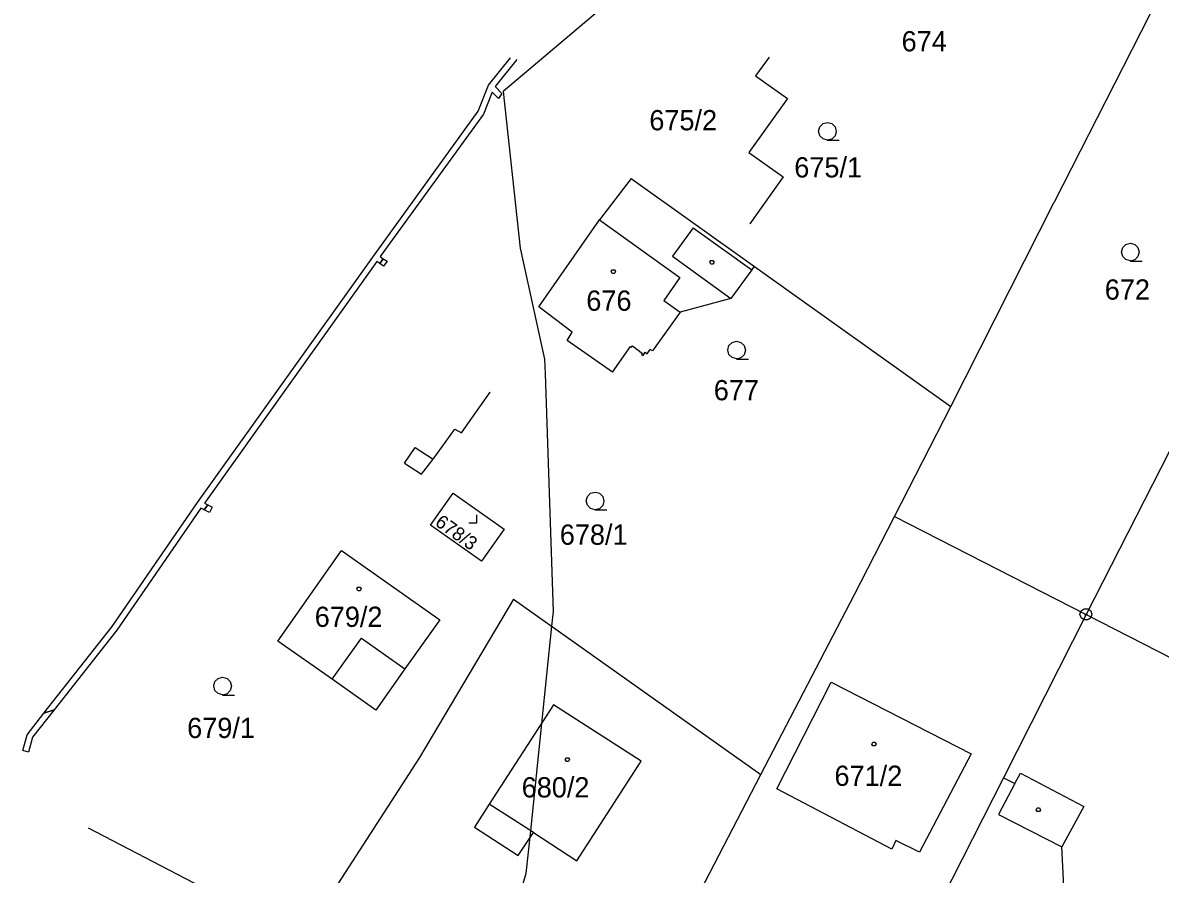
# Model space of a CAD drawing. Extents: x -759699 to -757730, y -1172308 to -1170857.
# Drawn here: x -758551.3 to -758455.8, y -1171287.4 to -1171215.9 of the extents above; entities that cross this region are included whole.
import ezdxf

# ---------------------------------------------------------------- set-up
doc = ezdxf.new("R2010")
doc.units = 0
for name, color, linetype in [('Vrstva 1', 7, 'Continuous'), ('Vrstva 11', 7, 'Continuous'), ('Vrstva 12', 7, 'Continuous'), ('Vrstva 13', 7, 'Continuous'), ('Vrstva 2', 7, 'Continuous'), ('Vrstva 3', 7, 'Continuous'), ('Vrstva 4', 7, 'Continuous'), ('Vrstva 5', 7, 'Continuous'), ('Vrstva 8', 7, 'Continuous')]:
    doc.layers.add(name, color=color, linetype=linetype)

msp = doc.modelspace()

# ---------------------------------------------------------------- linework, layer by layer
at = {"layer": 'Vrstva 1'}
for p, q in [((-758453.47, -1171208.89), (-758458.92, -1171219.58)), ((-758437.39, -1171217.28), (-758462.04, -1171265.57)), ((-758488.65, -1171218.77), (-758489.78, -1171220.35)), ((-758488.65, -1171218.77), (-758488.65, -1171218.77)), ((-758458.92, -1171219.58), (-758464.71, -1171230.94)), ((-758458.92, -1171219.58), (-758458.92, -1171219.58)), ((-758489.78, -1171220.35), (-758487.11, -1171222.26)), ((-758487.11, -1171222.26), (-758490.34, -1171226.79)), ((-758490.34, -1171226.79), (-758487.46, -1171228.84)), ((-758500.23, -1171228.97), (-758502.9, -1171232.43)), ((-758500.23, -1171228.97), (-758500.23, -1171228.97)), ((-758500.23, -1171228.97), (-758489.88, -1171236.35)), ((-758487.46, -1171228.84), (-758490.26, -1171232.78)), ((-758473.39, -1171248.12), (-758464.71, -1171230.94)), ((-758464.71, -1171230.94), (-758464.71, -1171230.94)), ((-758507.99, -1171239.75), (-758502.9, -1171232.43)), ((-758490.26, -1171232.78), (-758490.26, -1171232.78)), ((-758490.09, -1171236.64), (-758491.86, -1171239.04)), ((-758490.09, -1171236.64), (-758489.88, -1171236.35)), ((-758489.88, -1171236.35), (-758473.39, -1171248.12)), ((-758505.17, -1171241.87), (-758507.99, -1171239.75)), ((-758491.86, -1171239.04), (-758496.12, -1171240.18)), ((-758496.12, -1171240.18), (-758498.45, -1171243.44)), ((-758505.6, -1171242.57), (-758505.17, -1171241.87)), ((-758501.81, -1171245.24), (-758505.6, -1171242.57)), ((-758501.81, -1171245.24), (-758500.28, -1171243.08)), ((-758500.28, -1171243.08), (-758500.2, -1171243.14)), ((-758500.2, -1171243.14), (-758500.12, -1171243.02)), ((-758500.12, -1171243.02), (-758499.29, -1171243.65)), ((-758499.29, -1171243.65), (-758499.35, -1171243.73)), ((-758499.35, -1171243.73), (-758499.23, -1171243.82)), ((-758499.23, -1171243.82), (-758499.05, -1171243.56)), ((-758499.05, -1171243.56), (-758498.89, -1171243.68)), ((-758498.89, -1171243.68), (-758498.62, -1171243.32)), ((-758498.45, -1171243.44), (-758498.62, -1171243.32)), ((-758514.46, -1171250.32), (-758512.08, -1171246.92)), ((-758512.08, -1171246.92), (-758512.08, -1171246.92)), ((-758478.12, -1171257.35), (-758473.39, -1171248.12)), ((-758516.86, -1171252.53), (-758515.03, -1171250.02)), ((-758515.03, -1171250.02), (-758514.46, -1171250.32)), ((-758519.27, -1171252.86), (-758519.27, -1171252.86)), ((-758519.27, -1171252.86), (-758517.83, -1171253.8)), ((-758517.83, -1171253.8), (-758516.86, -1171252.53)), ((-758517.09, -1171258.09), (-758515.18, -1171255.4)), ((-758515.18, -1171255.4), (-758510.9, -1171258.42)), ((-758512.8, -1171261.11), (-758517.09, -1171258.09)), ((-758481.47, -1171263.91), (-758478.12, -1171257.35)), ((-758478.12, -1171257.35), (-758462.04, -1171265.57)), ((-758510.9, -1171258.42), (-758512.8, -1171261.11)), ((-758529.9, -1171267.82), (-758524.55, -1171260.21)), ((-758524.55, -1171260.21), (-758516.29, -1171266.02)), ((-758510.1, -1171264.29), (-758518.01, -1171277.59)), ((-758510.1, -1171264.29), (-758510.1, -1171264.29)), ((-758510.1, -1171264.29), (-758489.33, -1171279.02)), ((-758489.33, -1171279.02), (-758481.47, -1171263.91)), ((-758481.47, -1171263.91), (-758481.47, -1171263.91)), ((-758462.04, -1171265.57), (-758468.98, -1171279.28)), ((-758462.04, -1171265.57), (-758446, -1171273.82)), ((-758516.29, -1171266.02), (-758519.22, -1171270.15)), ((-758525.34, -1171271.02), (-758529.9, -1171267.82)), ((-758519.22, -1171270.15), (-758521.66, -1171273.6)), ((-758521.66, -1171273.6), (-758525.34, -1171271.02)), ((-758488.01, -1171280.22), (-758483.44, -1171271.25)), ((-758483.44, -1171271.25), (-758471.67, -1171277.27)), ((-758506.74, -1171273.15), (-758512.14, -1171281.5)), ((-758499.39, -1171277.9), (-758506.74, -1171273.15)), ((-758518.01, -1171277.59), (-758527.85, -1171292.83)), ((-758504.79, -1171286.25), (-758499.39, -1171277.9)), ((-758471.67, -1171277.27), (-758476.01, -1171285.54)), ((-758497.35, -1171294.4), (-758489.33, -1171279.02)), ((-758468.01, -1171279.77), (-758467.55, -1171278.89)), ((-758467.55, -1171278.89), (-758462.22, -1171281.69)), ((-758468.98, -1171279.28), (-758477.15, -1171295.43)), ((-758468.98, -1171279.28), (-758468.01, -1171279.77)), ((-758478.35, -1171285.27), (-758488.01, -1171280.22)), ((-758508.44, -1171283.89), (-758512.14, -1171281.5)), ((-758462.22, -1171281.69), (-758464.06, -1171285.09)), ((-758545.78, -1171283.53), (-758545.78, -1171283.53)), ((-758545.78, -1171283.53), (-758545.78, -1171283.53)), ((-758527.85, -1171292.83), (-758545.78, -1171283.53)), ((-758508.44, -1171283.89), (-758504.79, -1171286.25)), ((-758478, -1171284.55), (-758478.35, -1171285.27)), ((-758476.01, -1171285.54), (-758478, -1171284.55)), ((-758463.83, -1171289.75), (-758464.06, -1171285.09))]:
    msp.add_line(p, q, dxfattribs=at)
at = {"layer": 'Vrstva 11'}
for p, q in [((-758128.76, -1170897.97), (-758510.97, -1171221.67)), ((-758510.97, -1171221.67), (-758509.56, -1171234.81)), ((-758509.56, -1171234.81), (-758507.5, -1171244.14)), ((-758507.5, -1171244.14), (-758507.46, -1171245.38)), ((-758507.46, -1171245.38), (-758506.79, -1171265.32)), ((-758506.79, -1171265.32), (-758506.92, -1171266.55)), ((-758506.92, -1171266.55), (-758507.76, -1171274.73)), ((-758507.76, -1171274.73), (-758508.69, -1171283.73)), ((-758508.69, -1171283.73), (-758509.06, -1171287.33)), ((-758509.06, -1171287.33), (-758512.09, -1171297.46))]:
    msp.add_line(p, q, dxfattribs=at)
at = {"layer": 'Vrstva 12'}
for p, q in [((-758488.65, -1171218.77), (-758489.78, -1171220.35)), ((-758488.65, -1171218.77), (-758488.65, -1171218.77)), ((-758489.78, -1171220.35), (-758487.11, -1171222.26)), ((-758487.11, -1171222.26), (-758490.34, -1171226.79)), ((-758490.34, -1171226.79), (-758487.46, -1171228.84)), ((-758487.46, -1171228.84), (-758490.26, -1171232.78)), ((-758507.99, -1171239.75), (-758502.9, -1171232.43)), ((-758502.9, -1171232.43), (-758496.13, -1171237.29)), ((-758490.26, -1171232.78), (-758490.26, -1171232.78)), ((-758496.13, -1171237.29), (-758497.5, -1171239.2)), ((-758505.17, -1171241.87), (-758507.99, -1171239.75)), ((-758497.5, -1171239.2), (-758496.12, -1171240.18)), ((-758496.12, -1171240.18), (-758498.45, -1171243.44)), ((-758505.6, -1171242.57), (-758505.17, -1171241.87)), ((-758501.81, -1171245.24), (-758505.6, -1171242.57)), ((-758501.81, -1171245.24), (-758500.28, -1171243.08)), ((-758500.28, -1171243.08), (-758500.2, -1171243.14)), ((-758500.2, -1171243.14), (-758500.12, -1171243.02)), ((-758500.12, -1171243.02), (-758499.29, -1171243.65)), ((-758499.29, -1171243.65), (-758499.35, -1171243.73)), ((-758499.35, -1171243.73), (-758499.23, -1171243.82)), ((-758499.23, -1171243.82), (-758499.05, -1171243.56)), ((-758499.05, -1171243.56), (-758498.89, -1171243.68)), ((-758498.89, -1171243.68), (-758498.62, -1171243.32)), ((-758498.45, -1171243.44), (-758498.62, -1171243.32)), ((-758514.46, -1171250.32), (-758512.08, -1171246.92)), ((-758512.08, -1171246.92), (-758512.08, -1171246.92)), ((-758516.86, -1171252.53), (-758515.03, -1171250.02)), ((-758515.03, -1171250.02), (-758514.46, -1171250.32)), ((-758519.27, -1171252.86), (-758518.35, -1171251.55)), ((-758518.35, -1171251.55), (-758516.86, -1171252.53)), ((-758519.27, -1171252.86), (-758519.27, -1171252.86)), ((-758529.9, -1171267.82), (-758524.55, -1171260.21)), ((-758524.55, -1171260.21), (-758516.29, -1171266.02)), ((-758516.29, -1171266.02), (-758519.22, -1171270.15)), ((-758525.34, -1171271.02), (-758522.87, -1171267.57)), ((-758522.87, -1171267.57), (-758519.22, -1171270.15)), ((-758525.34, -1171271.02), (-758529.9, -1171267.82)), ((-758488.01, -1171280.22), (-758483.44, -1171271.25)), ((-758483.44, -1171271.25), (-758471.67, -1171277.27)), ((-758506.74, -1171273.15), (-758512.14, -1171281.5)), ((-758499.39, -1171277.9), (-758506.74, -1171273.15)), ((-758504.79, -1171286.25), (-758499.39, -1171277.9)), ((-758471.67, -1171277.27), (-758476.01, -1171285.54)), ((-758478.35, -1171285.27), (-758488.01, -1171280.22)), ((-758508.44, -1171283.89), (-758512.14, -1171281.5)), ((-758508.44, -1171283.89), (-758504.79, -1171286.25)), ((-758478, -1171284.55), (-758478.35, -1171285.27)), ((-758476.01, -1171285.54), (-758478, -1171284.55))]:
    msp.add_line(p, q, dxfattribs=at)
at = {"layer": 'Vrstva 13'}
for p, q in [((-758512.22, -1171221.14), (-758510.35, -1171218.82)), ((-758510.35, -1171218.82), (-758510.35, -1171218.82)), ((-758509.83, -1171218.98), (-758511.66, -1171221.25)), ((-758509.83, -1171218.98), (-758509.83, -1171218.98)), ((-758513.08, -1171223.32), (-758512.22, -1171221.14)), ((-758511.91, -1171221.72), (-758512.64, -1171223.56)), ((-758511.38, -1171222.25), (-758511.91, -1171221.72)), ((-758511.66, -1171221.25), (-758511.08, -1171221.84)), ((-758511.08, -1171221.84), (-758511.38, -1171222.25)), ((-758521.93, -1171235.56), (-758513.08, -1171223.32)), ((-758512.64, -1171223.56), (-758521.29, -1171235.52)), ((-758536.63, -1171256.17), (-758521.93, -1171235.56)), ((-758521.58, -1171235.93), (-758536.06, -1171256.22)), ((-758521.33, -1171236.11), (-758521.58, -1171235.93)), ((-758521.33, -1171236.11), (-758521.04, -1171235.7)), ((-758521.04, -1171235.7), (-758521.33, -1171236.11)), ((-758521.02, -1171236.33), (-758521.33, -1171236.11)), ((-758521.29, -1171235.52), (-758521.04, -1171235.7)), ((-758521.04, -1171235.7), (-758520.72, -1171235.92)), ((-758520.72, -1171235.92), (-758521.02, -1171236.33)), ((-758543.81, -1171266.58), (-758536.63, -1171256.17)), ((-758536.35, -1171256.64), (-758543.41, -1171266.88)), ((-758536.07, -1171256.79), (-758536.35, -1171256.64)), ((-758536.07, -1171256.79), (-758535.77, -1171256.38)), ((-758535.77, -1171256.38), (-758536.07, -1171256.79)), ((-758535.64, -1171257.02), (-758536.07, -1171256.79)), ((-758536.06, -1171256.22), (-758535.77, -1171256.38)), ((-758535.77, -1171256.38), (-758535.4, -1171256.57)), ((-758535.4, -1171256.57), (-758535.64, -1171257.02)), ((-758549.53, -1171273.86), (-758543.81, -1171266.58)), ((-758543.41, -1171266.88), (-758548.67, -1171273.57)), ((-758550.95, -1171275.67), (-758549.53, -1171273.86)), ((-758548.67, -1171273.57), (-758550.49, -1171275.89)), ((-758548.67, -1171273.57), (-758549.53, -1171273.86)), ((-758549.53, -1171273.86), (-758548.67, -1171273.57)), ((-758551.31, -1171277.01), (-758550.95, -1171275.67)), ((-758550.49, -1171275.89), (-758550.83, -1171277.14)), ((-758550.83, -1171277.14), (-758551.31, -1171277.01))]:
    msp.add_line(p, q, dxfattribs=at)
at = {"layer": 'Vrstva 3'}
for points in [[(-758483.74, -1171225.74), (-758484.12, -1171225.64), (-758484.39, -1171225.37), (-758484.49, -1171225), (-758484.39, -1171224.63), (-758484.12, -1171224.36), (-758483.75, -1171224.26), (-758483.38, -1171224.36), (-758483.11, -1171224.63), (-758483.01, -1171225.01), (-758483.11, -1171225.39), (-758483.38, -1171225.66), (-758483.76, -1171225.76), (-758482.76, -1171225.76)], [(-758458.31, -1171235.88), (-758458.69, -1171235.78), (-758458.96, -1171235.51), (-758459.06, -1171235.14), (-758458.96, -1171234.77), (-758458.69, -1171234.5), (-758458.32, -1171234.4), (-758457.95, -1171234.5), (-758457.68, -1171234.77), (-758457.58, -1171235.15), (-758457.68, -1171235.53), (-758457.95, -1171235.8), (-758458.33, -1171235.9), (-758457.33, -1171235.9)], [(-758491.37, -1171244.11), (-758491.75, -1171244.01), (-758492.02, -1171243.74), (-758492.12, -1171243.37), (-758492.02, -1171243), (-758491.75, -1171242.73), (-758491.38, -1171242.63), (-758491.01, -1171242.73), (-758490.74, -1171243), (-758490.64, -1171243.38), (-758490.74, -1171243.76), (-758491.01, -1171244.03), (-758491.39, -1171244.13), (-758490.39, -1171244.13)], [(-758503.25, -1171256.78), (-758503.63, -1171256.68), (-758503.9, -1171256.41), (-758504, -1171256.04), (-758503.9, -1171255.67), (-758503.63, -1171255.4), (-758503.26, -1171255.3), (-758502.89, -1171255.4), (-758502.62, -1171255.67), (-758502.52, -1171256.05), (-758502.62, -1171256.43), (-758502.89, -1171256.7), (-758503.27, -1171256.8), (-758502.27, -1171256.8)], [(-758513.855, -1171257.89), (-758513.185, -1171257.89), (-758513.185, -1171257.22)], [(-758534.52, -1171272.32), (-758534.9, -1171272.22), (-758535.17, -1171271.95), (-758535.27, -1171271.58), (-758535.17, -1171271.21), (-758534.9, -1171270.94), (-758534.53, -1171270.84), (-758534.16, -1171270.94), (-758533.89, -1171271.21), (-758533.79, -1171271.59), (-758533.89, -1171271.97), (-758534.16, -1171272.24), (-758534.54, -1171272.34), (-758533.54, -1171272.34)]]:
    msp.add_lwpolyline(points, dxfattribs=at)
at = {"layer": 'Vrstva 4'}
for p, q in [((-758502.9, -1171232.43), (-758496.13, -1171237.29)), ((-758495.03, -1171233.1), (-758496.75, -1171235.5)), ((-758495.03, -1171233.1), (-758490.09, -1171236.64)), ((-758496.75, -1171235.5), (-758491.86, -1171239.04)), ((-758496.13, -1171237.29), (-758497.5, -1171239.2)), ((-758497.5, -1171239.2), (-758496.12, -1171240.18)), ((-758519.27, -1171252.86), (-758518.35, -1171251.55)), ((-758518.35, -1171251.55), (-758516.86, -1171252.53)), ((-758525.34, -1171271.02), (-758522.87, -1171267.57)), ((-758522.87, -1171267.57), (-758519.22, -1171270.15)), ((-758468.01, -1171279.77), (-758469.38, -1171282.36)), ((-758512.14, -1171281.5), (-758513.39, -1171283.44)), ((-758469.38, -1171282.36), (-758464.06, -1171285.09)), ((-758513.39, -1171283.44), (-758509.71, -1171285.81)), ((-758509.71, -1171285.81), (-758508.44, -1171283.89))]:
    msp.add_line(p, q, dxfattribs=at)
at = {"layer": 'Vrstva 5'}
for points in [[(-758493.36, -1171235.85), (-758493.27, -1171236), (-758493.36, -1171236.15), (-758493.54, -1171236.15), (-758493.63, -1171236), (-758493.54, -1171235.85)], [(-758501.64, -1171236.63), (-758501.55, -1171236.78), (-758501.64, -1171236.93), (-758501.82, -1171236.93), (-758501.91, -1171236.78), (-758501.82, -1171236.63)], [(-758522.99, -1171263.28), (-758522.9, -1171263.43), (-758522.99, -1171263.58), (-758523.17, -1171263.58), (-758523.26, -1171263.43), (-758523.17, -1171263.28)], [(-758479.76, -1171276.31), (-758479.67, -1171276.46), (-758479.76, -1171276.61), (-758479.94, -1171276.61), (-758480.03, -1171276.46), (-758479.94, -1171276.31)], [(-758505.49, -1171277.61), (-758505.4, -1171277.76), (-758505.49, -1171277.91), (-758505.67, -1171277.91), (-758505.76, -1171277.76), (-758505.67, -1171277.61)], [(-758465.96, -1171281.82), (-758465.87, -1171281.97), (-758465.96, -1171282.12), (-758466.14, -1171282.12), (-758466.23, -1171281.97), (-758466.14, -1171281.82)]]:
    msp.add_lwpolyline(points, close=True, dxfattribs=at)
at = {"layer": 'Vrstva 8'}
msp.add_line((-758462.16, -1171265.57), (-758461.92, -1171265.57), dxfattribs=at)
msp.add_lwpolyline([(-758461.89, -1171265.09), (-758461.64, -1171265.27), (-758461.54, -1171265.56), (-758461.64, -1171265.85), (-758461.89, -1171266.03), (-758462.2, -1171266.03), (-758462.45, -1171265.85), (-758462.55, -1171265.56), (-758462.45, -1171265.27), (-758462.2, -1171265.09)], close=True, dxfattribs=at)

# ---------------------------------------------------------------- texts
at = {"layer": 'Vrstva 2'}
for s, p in [('674', (-758477.524, -1171218.29)), ('675/2', (-758498.704, -1171224.92)), ('675/1', (-758486.532, -1171228.88)), ('672', (-758460.468, -1171239.14)), ('676', (-758503.994, -1171240.07)), ('677', (-758493.294, -1171247.59)), ('678/1', (-758506.222, -1171259.72)), ('679/2', (-758526.797, -1171266.62)), ('679/1', (-758537.505, -1171275.95)), ('671/2', (-758483.159, -1171279.97)), ('680/2', (-758509.42, -1171280.94))]:
    msp.add_text(s, height=1.7, dxfattribs=at).set_placement(p)
msp.add_text('678/3', height=1.14, rotation=324.52329, dxfattribs=at).set_placement((-758516.775, -1171258.035))

doc.saveas('drawing.dxf')
